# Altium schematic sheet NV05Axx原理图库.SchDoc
size 127 x 99 mm
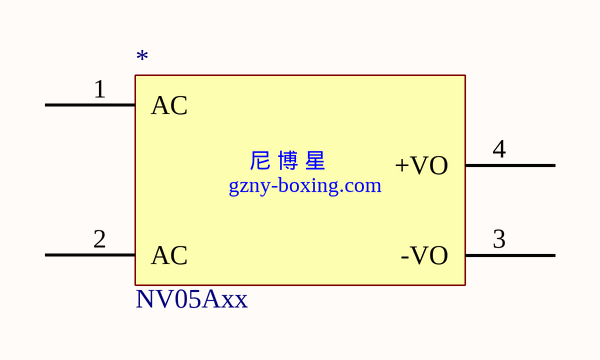
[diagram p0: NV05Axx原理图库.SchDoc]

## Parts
*  NV05Axx

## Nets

Not connected (* = marked no-connect by the designer): * 1(AC) 2(AC) 3(-VO) 4(+VO)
